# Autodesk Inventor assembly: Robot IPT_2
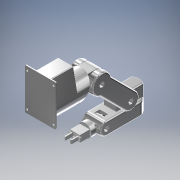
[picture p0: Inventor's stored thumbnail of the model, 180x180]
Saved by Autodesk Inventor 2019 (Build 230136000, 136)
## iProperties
Created: 2018-07
Part Number: Robot IPT_2
Document SubType Name: Assembly
Designer: Power User
Author: Power User
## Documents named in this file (10)
- D:\Karntarat T\06.MFG_Autodesk Inventor file\03.Project Test_byKarn\Practics\Robot IPT\Robot IPT_2.iam
- D:\Karntarat T\06.MFG_Autodesk Inventor file\03.Project Test_byKarn\Practics\Robot IPT\Robot-Base-Model-A.ipt
- D:\Karntarat T\06.MFG_Autodesk Inventor file\03.Project Test_byKarn\Practics\Robot IPT\Robot-Axis1-1.ipt
- D:\Karntarat T\06.MFG_Autodesk Inventor file\03.Project Test_byKarn\Practics\Robot IPT\Robot-Axis1-2.ipt
- D:\Karntarat T\06.MFG_Autodesk Inventor file\03.Project Test_byKarn\Practics\Robot IPT\Robot-Axis1-3.ipt
- D:\Karntarat T\06.MFG_Autodesk Inventor file\03.Project Test_byKarn\Practics\Robot IPT\Robot-Axis1-4.ipt
- D:\Karntarat T\06.MFG_Autodesk Inventor file\03.Project Test_byKarn\Practics\Robot IPT\Robot-Axis1-5.ipt
- D:\Karntarat T\06.MFG_Autodesk Inventor file\03.Project Test_byKarn\Practics\Robot IPT\Robot-Axis1-6.ipt
- D:\Karntarat T\06.MFG_Autodesk Inventor file\03.Project Test_byKarn\Practics\Robot IPT\Robot-Clamp.ipt
- D:\Karntarat T\06.MFG_Autodesk Inventor file\03.Project Test_byKarn\Practics\Robot IPT\Robot-Clamp-Mount.ipt
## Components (10 placed, 9 different names)
1. Robot-Base-Model-A:1 — Insert:1, Angle:1, Mate:7
2. Robot-Axis1-1:1 — Insert:1, Insert:2, Mate:7
3. Robot-Axis1-2:1 — Insert:2, Insert:3, Angle:1, Angle:2
4. Robot-Axis1-3:1 — Insert:3, Insert:4, Mate:8, Angle:2
5. Robot-Axis1-4:1 — Insert:4, Insert:5, Mate:8, Mate:9, Mate:10, Angle:3
6. Robot-Axis1-5:1 — Insert:5, Mate:1, Mate:2
7. Robot-Axis1-6:1 — Mate:1, Mate:2, Insert:6, Mate:9
8. Robot-Clamp:1 — Mate:3, Mate:4, Flush:1
9. Robot-Clamp-Mount:1 — Insert:6, Mate:3, Mate:4, Flush:1, Mate:5, Mate:6, Flush:2, Mate:10, Angle:3
10. Robot-Clamp:2 — Mate:5, Mate:6, Flush:2
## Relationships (21: Mate 10, Insert 6, Angle 3, Flush 2)
- Insert:1: Robot-Base-Model-A:1 ↔ Robot-Axis1-1:1
- Insert:2: Robot-Axis1-1:1 ↔ Robot-Axis1-2:1
- Insert:3: Robot-Axis1-2:1 ↔ Robot-Axis1-3:1
- Insert:4: Robot-Axis1-3:1 ↔ Robot-Axis1-4:1
- Insert:5: Robot-Axis1-4:1 ↔ Robot-Axis1-5:1
- Mate:1: Robot-Axis1-5:1 ↔ Robot-Axis1-6:1
- Mate:2: Robot-Axis1-5:1 ↔ Robot-Axis1-6:1
- Insert:6: Robot-Axis1-6:1 ↔ Robot-Clamp-Mount:1
- Mate:3: Robot-Clamp:1 ↔ Robot-Clamp-Mount:1
- Mate:4: Robot-Clamp:1 ↔ Robot-Clamp-Mount:1
- Flush:1: Robot-Clamp:1 ↔ Robot-Clamp-Mount:1
- Mate:5: Robot-Clamp-Mount:1 ↔ Robot-Clamp:2
- Mate:6: Robot-Clamp-Mount:1 ↔ Robot-Clamp:2
- Flush:2: Robot-Clamp-Mount:1 ↔ Robot-Clamp:2
- Angle:1: Robot-Base-Model-A:1 ↔ Robot-Axis1-2:1
- Mate:7: Robot-Base-Model-A:1 ↔ Robot-Axis1-1:1
- Mate:8: Robot-Axis1-3:1 ↔ Robot-Axis1-4:1
- Angle:2: Robot-Axis1-2:1 ↔ Robot-Axis1-3:1
- Mate:9: Robot-Axis1-4:1 ↔ Robot-Axis1-6:1
- Mate:10: Robot-Axis1-4:1 ↔ Robot-Clamp-Mount:1
- Angle:3: Robot-Axis1-4:1 ↔ Robot-Clamp-Mount:1
